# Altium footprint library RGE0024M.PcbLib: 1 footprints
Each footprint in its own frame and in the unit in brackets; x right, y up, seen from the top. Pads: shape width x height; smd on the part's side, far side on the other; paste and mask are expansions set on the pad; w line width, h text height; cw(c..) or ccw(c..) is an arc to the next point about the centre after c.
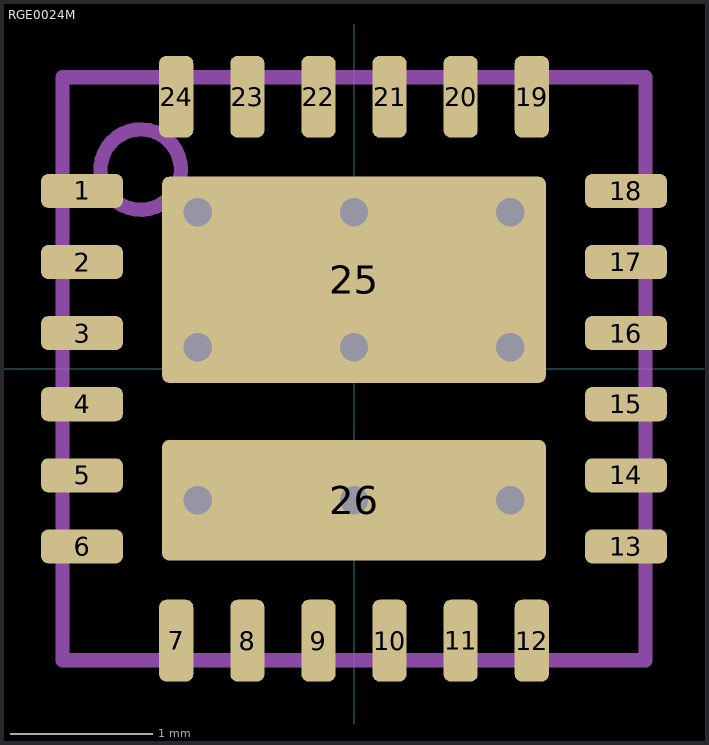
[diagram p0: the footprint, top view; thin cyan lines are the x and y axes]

## RGE0024M [mm] "VQFN-24"
height 1
pads (26):
  rrect42% 0.575x0.24 smd: 1(-1.913,1.25) 2(-1.913,0.75) 3(-1.913,0.25) 4(-1.913,-0.25) 5(-1.913,-0.75) 6(-1.913,-1.25) 13(1.913,-1.25) 14(1.913,-0.75) 15(1.913,-0.25) 16(1.913,0.25) 17(1.913,0.75) 18(1.913,1.25)
  rrect42% 0.24x0.575 smd: 7(-1.25,-1.912) 8(-0.75,-1.912) 9(-0.25,-1.912) 10(0.25,-1.912) 11(0.75,-1.912) 12(1.25,-1.912) 19(1.25,1.913) 20(0.75,1.913) 21(0.25,1.913) 22(-0.25,1.913) 23(-0.75,1.913) 24(-1.25,1.913)
  rrect7% 2.7x1.45 smd paste-3: 25(0,0.625)
  rrect12% 2.7x0.85 smd paste-3: 26(0,-0.925)
via 1.1,-0.925 diameter 0.5 hole 0.2
via 0,-0.925 diameter 0.5 hole 0.2
via -1.1,-0.925 diameter 0.5 hole 0.2
via 1.1,1.1 diameter 0.5 hole 0.2
via -1.1,1.1 diameter 0.5 hole 0.2
via 0,0.15 diameter 0.5 hole 0.2
via 0,1.1 diameter 0.5 hole 0.2
via -1.1,0.15 diameter 0.5 hole 0.2
via 1.1,0.15 diameter 0.5 hole 0.2
Top Paste:
  region: -0.1,-1.255 -0.1,-0.595 -0.1,-0.585 -0.108,-0.567 -0.122,-0.553 -0.14,-0.545 -0.15,-0.545 -1.238,-0.545 -1.248,-0.545 -1.266,-0.553 -1.28,-0.567 -1.288,-0.585 -1.288,-0.595 -1.288,-1.255 -1.288,-1.265 -1.28,-1.283 -1.266,-1.297 -1.248,-1.305 -1.238,-1.305 -0.15,-1.305 -0.14,-1.305 -0.122,-1.297 -0.108,-1.283 -0.1,-1.265
  region: 0.1,-1.255 0.1,-0.595 0.1,-0.585 0.108,-0.567 0.122,-0.553 0.14,-0.545 0.15,-0.545 1.238,-0.545 1.248,-0.545 1.266,-0.553 1.28,-0.567 1.288,-0.585 1.288,-0.595 1.288,-1.255 1.288,-1.265 1.28,-1.283 1.266,-1.297 1.248,-1.305 1.238,-1.305 0.15,-1.305 0.14,-1.305 0.122,-1.297 0.108,-1.283 0.1,-1.265
  region: -0.1,0.025 -0.1,1.225 -0.1,1.235 -0.108,1.253 -0.122,1.267 -0.14,1.275 -0.15,1.275 -1.238,1.275 -1.248,1.275 -1.266,1.267 -1.28,1.253 -1.288,1.235 -1.288,1.225 -1.288,0.025 -1.288,0.015 -1.28,-0.003 -1.266,-0.017 -1.248,-0.025 -1.238,-0.025 -0.15,-0.025 -0.14,-0.025 -0.122,-0.017 -0.108,-0.003 -0.1,0.015
  region: 0.1,0.025 0.1,1.225 0.1,1.235 0.108,1.253 0.122,1.267 0.14,1.275 0.15,1.275 1.238,1.275 1.248,1.275 1.266,1.267 1.28,1.253 1.288,1.235 1.288,1.225 1.288,0.025 1.288,0.015 1.28,-0.003 1.266,-0.017 1.248,-0.025 1.238,-0.025 0.15,-0.025 0.14,-0.025 0.122,-0.017 0.108,-0.003 0.1,0.015
M5 Assembly Top:
  circle w0.1: c-1.5,1.4 r0.283
  lines w0.1: -2.05,-2.05 -2.05,2.05 2.05,2.05 2.05,-2.05 -2.05,-2.05
  text ".Designator" at -1.4,-0.3 h0.8
3D body "RGE0024M.stp": height 1, standoff 0, extent -2,-2 2,2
